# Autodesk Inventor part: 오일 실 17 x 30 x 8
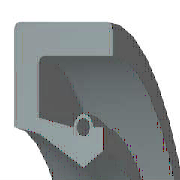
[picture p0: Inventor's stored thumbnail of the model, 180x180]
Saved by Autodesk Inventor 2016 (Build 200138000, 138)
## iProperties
IsCustomPart: 1
Created: 2012-02
Part Number: 오일 실 17 x 30 x 8
Material: 고무
Description: 오일 실 - 스프링 장착, 금속 케이스 SM
Document SubType Name: Modeling
Standard: JIS B 2402
Designer: mdu-01
Standards Organization: JIS
Language: ko-KR
Size Designation: 17 30 8 A
Categories: <MemberInstance><Categories><Category DisplayName="샤프트 부품" InternalName="7f7aeb1f-a693-4053-b835-cee3144e0d98" Mnemonic="SHFT"><Category DisplayName="실링" Intern
Density: 0.93 g/cm^3
Appearance: Rubber-Black
Author: mdu-01
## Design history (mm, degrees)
body "Solid1"
revolve "회전1" stored, may be unused: angle "d33" = 360 deg
fillet "모깎기1" dims "d34" = 0.4 (= 0.05 x b)
chamfer "모따기1" distance "d35" = 0.8 (= 0.1 x b); stored, may be unused: second distance "d36" = 0.4 (= 0.05 x b), angle "d41" = 45 deg
sketch "스케치2"
  geometry: L1 (10.079, -5.895)-(10.689, -8); L2 (9.429, -5.2)-(10.079, -5.895); L3 (8.5, -2)-(9.429, -5.2); L4 (9.367, -1)-(8.5, -2); L5 (10.819, -1)-(9.367, -1); L6 (10.819, -1.8)-(10.819, -1); L7 (10.819, -6)-(10.819, -3.4); L8 (12.4, -6)-(10.819, -6); L9 (13.7, -2)-(12.4, -6); L10 (13.7, 0)-(13.7, -2); L11 (15, 0)-(13.7, 0); L12 (15, -8)-(15, 0); L13 (10.689, -8)-(15, -8); L14 (0, -9.6)-(0, 1.6) reference; L15 (28, 0)-(14, 0) reference; A1 r 0.8 centre (10.819, -2.6) between (10.819, -3.4) and (10.819, -1.8)
  constraints: 26 end point, 4 horizontal, 4 vertical, 2 point on circle, 1 centre point, 1 collinear, 1 parallel
  dimensions: "d2" = 8 distance of L12.start L11.start (= b); "d4" = 1 vertical distance of L10.start L5.start (= 0.125 x b); "d6" = 1.3 distance of L11.start L10.start (= 0.1 x dd - 0.1 x Diam); "d8" = 2 distance of L10.start L9.start (= 0.25 x b); "d10" = 2 vertical distance of L8.start L1.end (= 0.25 x b); "d12" = 1.3 horizontal distance of L9.start L8.start (= 0.1 x dd - 0.1 x Diam); "d14" = 0.8 radius of A1 (= 0.1 x b); "d16" = 0 horizontal distance of A1.centre L7.end; "d18" = 0.8 distance of L6.start L5.start (= 0.1 x b); "d20" = 0.86667 horizontal distance of L4.start L3.start (= 0.0666667 x dd - 0.0666667 x Diam); "d22" = 0.13 horizontal distance of L7.start L1.end (= 0.01 x dd - 0.01 x Diam); "d24" = 1 vertical distance of L4.start L3.start (= 0.125 x b); "d26" = 3.2 vertical distance of L3.start L2.start (= 0.4 x b); "d28" = 0.92857 horizontal distance of L3.start L2.start (= 0.0714286 x dd - 0.0714286 x Diam); "d30" = 2.10526 vertical distance of L1.start L1.end (= 0.263158 x b); "d32" = 0.65 horizontal distance of L2.start L1.start (= 0.05 x dd - 0.05 x Diam); "d37" = 0 distance between parallel lines of L15 L11; "d38" = 15 distance between parallel lines of L14 L12 (= 0.5 x dd); "d39" = 8.5 distance from line of L14 L3.start (= 0.5 x Diam)
other parameters: "Diam" = 17 [user parameter; used in 7 equation terms], "b" = 8 [user parameter; used in 12 equation terms], "d1" = 8 (derived), "d3" = 1 (derived), "d5" = 2 (derived), "d7" = 2 (derived), "d9" = 2 (derived), "d11" = 2 (derived), "d13" = 0.8 (derived), "d15" = 0 (derived), "d17" = 0.8 (derived), "d19" = 1.33333 (derived), "d21" = 0.2 (derived), "d23" = 1 (derived), "d25" = 3.2 (derived), "d27" = 1.42857 (derived), "d29" = 2.10526 (derived), "d31" = 1 (derived), "d40" = 0
